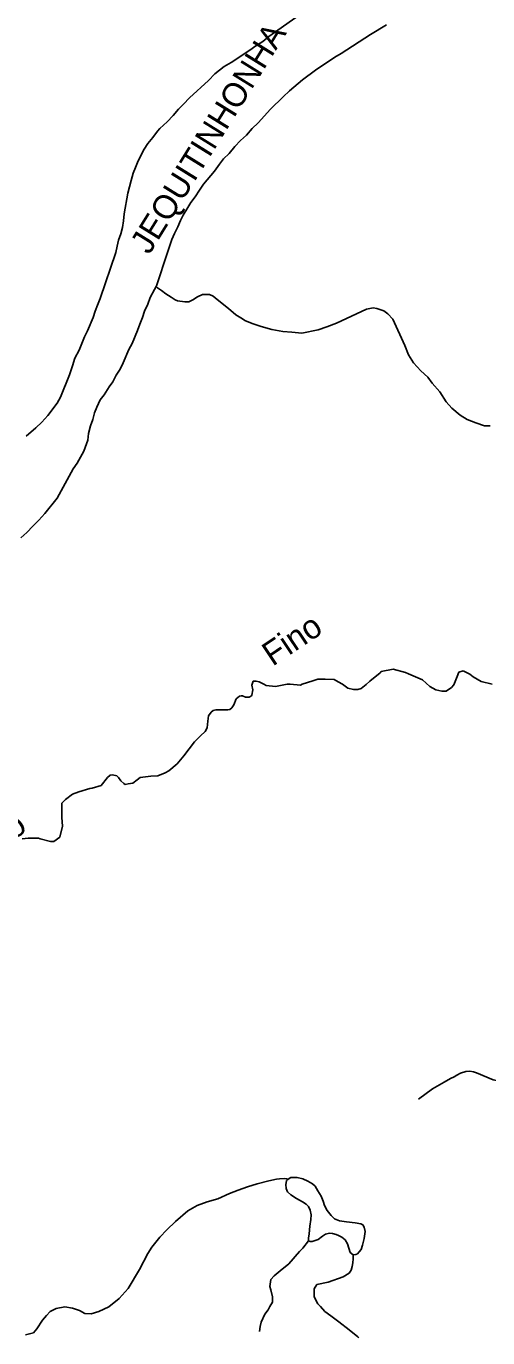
# Model space of a CAD drawing. Extents: x 436.3 to 500.4, y 8231 to 8286.4.
# Drawn here: x 485.33 to 489.18, y 8231.04 to 8241.98 of the extents above; entities that cross this region are included whole.
import ezdxf
from ezdxf.enums import TextEntityAlignment as Align

# ---------------------------------------------------------------- set-up
doc = ezdxf.new("R2010")
doc.units = 0
doc.header["$LTSCALE"] = 0.08
doc.linetypes.add('LONG_DASHED', pattern=[7.5, 6, -1.5])
doc.layers.add('2', color=7, linetype='Continuous', lineweight=25)
doc.layers.add('9', color=7, linetype='LONG_DASHED', lineweight=25)
doc.layers.add('61', color=7, linetype='Continuous')

msp = doc.modelspace()

# ---------------------------------------------------------------- linework, layer by layer
at = {"layer": '2'}
for points in [[(485.328, 8238.5583), (485.4095, 8238.6256), (485.4594, 8238.675), (485.5093, 8238.7289), (485.5864, 8238.8321), (485.6136, 8238.8815), (485.6881, 8239.0689), (485.7137, 8239.1424), (485.7347, 8239.2068), (485.7696, 8239.2757), (485.8137, 8239.3849), (485.8409, 8239.4343), (485.8864, 8239.5467), (485.9045, 8239.6007), (485.9227, 8239.6501), (485.9454, 8239.7041), (486.0754, 8240.0881), (486.086, 8240.1406), (486.0995, 8240.1901), (486.1176, 8240.2442), (486.1312, 8240.2982), (486.1403, 8240.3522), (486.1448, 8240.4108), (486.1764, 8240.582), (486.2035, 8240.6902), (486.2215, 8240.7488), (486.2395, 8240.7983), (486.2621, 8240.8524), (486.3117, 8240.9515), (486.3433, 8240.9966), (486.3839, 8241.0461), (486.4245, 8241.1001), (486.4425, 8241.1227), (486.5057, 8241.1767), (486.5553, 8241.2307), (486.6004, 8241.2848), (486.6409, 8241.3253), (486.6905, 8241.3793), (486.8483, 8241.5235), (486.9023, 8241.5775), (486.9789, 8241.6406), (487.0376, 8241.6721), (487.1953, 8241.7756), (487.2448, 8241.8117), (487.3034, 8241.8477), (487.3529, 8241.8882), (487.6255, 8242.0822)], [(486.4121, 8239.8049), (486.416, 8239.812), (486.5076, 8240.0897), (486.5425, 8240.1982), (486.5651, 8240.2477), (486.5922, 8240.3017), (486.6148, 8240.3558), (486.6374, 8240.4008), (486.669, 8240.4503), (486.7006, 8240.5043), (486.7368, 8240.5538), (486.7729, 8240.6079), (486.809, 8240.6574), (486.8992, 8240.7654), (486.9398, 8240.824), (486.9759, 8240.869), (487.021, 8240.914), (487.0705, 8240.9726), (487.1156, 8241.0221), (487.1652, 8241.0672), (487.2147, 8241.1212), (487.2643, 8241.1708), (487.3678, 8241.2835), (487.4713, 8241.3871), (487.5253, 8241.4367), (487.6333, 8241.5269), (487.7413, 8241.6081), (487.9033, 8241.7163), (487.9572, 8241.7479), (488.2, 8241.9058), (488.3349, 8241.987)], [(485.2845, 8237.7095), (485.3343, 8237.7544), (485.3842, 8237.8082), (485.4341, 8237.8575), (485.484, 8237.9114), (485.5861, 8238.0404), (485.7211, 8238.2837), (485.752, 8238.3332), (485.8087, 8238.4329), (485.8436, 8238.5247), (485.8477, 8238.5801), (485.866, 8238.643), (485.8842, 8238.6969), (485.8979, 8238.7508), (485.9162, 8238.8002), (485.9457, 8238.8597), (485.9782, 8238.901), (486.02, 8238.9677), (486.0502, 8239.0113), (486.0796, 8239.0652), (486.1114, 8239.1146), (486.1386, 8239.1685), (486.1841, 8239.2808), (486.2113, 8239.3302), (486.2568, 8239.4381), (486.275, 8239.492), (486.2977, 8239.546), (486.3158, 8239.5999), (486.343, 8239.6584), (486.3612, 8239.7123), (486.3987, 8239.7805), (486.4121, 8239.8049)], [(488.0579, 8231.7323), (488.0793, 8231.7345), (488.0922, 8231.7409), (488.1071, 8231.7559), (488.1221, 8231.7773), (488.1349, 8231.8116), (488.1498, 8231.8693), (488.1561, 8231.9271), (488.1474, 8231.9635), (488.1366, 8231.9827), (488.1216, 8231.9912), (488.0744, 8231.9976), (488.0015, 8232.006), (487.9414, 8232.0145), (487.9006, 8232.0315), (487.8726, 8232.0594), (487.8403, 8232.1021), (487.8187, 8232.1427), (487.8057, 8232.179), (487.7884, 8232.2196), (487.7626, 8232.2667), (487.7409, 8232.3031), (487.7172, 8232.3244), (487.6785, 8232.3457), (487.6377, 8232.365), (487.5904, 8232.3756), (487.5581, 8232.3778), (487.5336, 8232.3759), (487.5302, 8232.3744), (487.5112, 8232.3607)], [(487.5112, 8232.3607), (487.5002, 8232.3499), (487.496, 8232.3178), (487.4983, 8232.2856), (487.5091, 8232.2579), (487.5372, 8232.2323), (487.5845, 8232.2002), (487.634, 8232.1724), (487.6641, 8232.1554), (487.6835, 8232.134), (487.6986, 8232.1041), (487.7052, 8232.0656), (487.7031, 8232.027), (487.6946, 8231.9715), (487.6883, 8231.9073), (487.6831, 8231.8705), (487.6847, 8231.8492)], [(487.6847, 8231.8492), (487.6992, 8231.8431), (487.7142, 8231.8431), (487.7314, 8231.8474), (487.7636, 8231.8603), (487.8, 8231.8881), (487.8257, 8231.9052), (487.8601, 8231.9118), (487.8837, 8231.9096), (487.9138, 8231.9011), (487.9352, 8231.8926), (487.9611, 8231.8797), (487.9889, 8231.8563), (488.0083, 8231.8242), (488.0192, 8231.7879), (488.032, 8231.7515), (488.0579, 8231.7323)]]:
    msp.add_lwpolyline(points, dxfattribs=at)
at = {"layer": '9'}
msp.add_line((486.4231, 8239.7953), (486.4121, 8239.8049), dxfattribs=at)
for points in [[(489.2012, 8238.6429), (489.1521, 8238.6448), (489.0805, 8238.6672), (489.007, 8238.6956), (488.9498, 8238.7323), (488.8804, 8238.7914), (488.8336, 8238.8443), (488.7807, 8238.9259), (488.7172, 8239.0005), (488.6805, 8239.0494), (488.6214, 8239.1025), (488.5602, 8239.1697), (488.5173, 8239.2351), (488.4869, 8239.3127), (488.3878, 8239.5318), (488.345, 8239.5786), (488.3122, 8239.6032), (488.2528, 8239.6216), (488.2241, 8239.6276), (488.1667, 8239.6174), (487.9162, 8239.4987), (487.8381, 8239.468), (487.7641, 8239.4435), (487.6285, 8239.417), (487.5443, 8239.4231), (487.4703, 8239.4313), (487.3784, 8239.4462), (487.29, 8239.4708), (487.2222, 8239.4934), (487.1585, 8239.5201), (487.1195, 8239.5426), (487.0784, 8239.5693), (487.0168, 8239.6205), (486.9222, 8239.6964), (486.8873, 8239.7252), (486.8585, 8239.7375), (486.8338, 8239.7396), (486.7988, 8239.7376), (486.7576, 8239.7192), (486.7184, 8239.6947), (486.6855, 8239.6784), (486.6505, 8239.6764), (486.5908, 8239.6847), (486.5723, 8239.6929), (486.5373, 8239.7155), (486.4941, 8239.7443), (486.4571, 8239.771), (486.4231, 8239.7953)], [(486.369, 8235.7223), (486.4269, 8235.7262), (486.4885, 8235.7491), (486.5193, 8235.7683), (486.5888, 8235.8257), (486.6428, 8235.8908), (486.7315, 8236.0094), (486.7831, 8236.0601), (486.8217, 8236.0946), (486.8371, 8236.1252), (486.8449, 8236.1825), (486.8488, 8236.2247), (486.872, 8236.2552), (486.8874, 8236.2706), (486.9106, 8236.2744), (487.0107, 8236.2744), (487.0261, 8236.2783), (487.0454, 8236.2936), (487.0608, 8236.3165), (487.0802, 8236.3662), (487.1072, 8236.3892), (487.1225, 8236.3931), (487.1342, 8236.3931), (487.1572, 8236.3816), (487.188, 8236.3817), (487.2073, 8236.3931), (487.2112, 8236.3969), (487.219, 8236.4429), (487.2113, 8236.4811), (487.2229, 8236.5156), (487.2461, 8236.5156), (487.2729, 8236.5079), (487.3115, 8236.4888), (487.3314, 8236.4783), (487.4084, 8236.4707), (487.5046, 8236.49), (487.5315, 8236.49), (487.6162, 8236.4824), (487.6316, 8236.4901), (487.7201, 8236.5169), (487.7625, 8236.5323), (487.824, 8236.5324), (487.8971, 8236.5286), (487.9317, 8236.5095), (487.9663, 8236.4905), (488.0122, 8236.4561), (488.0584, 8236.4447), (488.0968, 8236.4447), (488.1237, 8236.4525), (488.1661, 8236.4869), (488.1969, 8236.5138), (488.283, 8236.5834), (488.2908, 8236.5948), (488.3907, 8236.6141), (488.4944, 8236.5875), (488.5173, 8236.5761), (488.6363, 8236.5266), (488.6977, 8236.4694), (488.7475, 8236.4427), (488.7973, 8236.4314), (488.8319, 8236.4314), (488.878, 8236.4621), (488.8972, 8236.4851), (488.9242, 8236.554), (488.9396, 8236.5884), (488.9742, 8236.5999), (489.0316, 8236.5734), (489.0585, 8236.5505), (489.1236, 8236.5124), (489.2156, 8236.4897)], [(485.2949, 8235.1998), (485.345, 8235.207), (485.431, 8235.207), (485.4454, 8235.1998), (485.5313, 8235.1785), (485.56, 8235.1785), (485.61, 8235.214), (485.6314, 8235.3064), (485.6242, 8235.3775), (485.6241, 8235.4983), (485.6555, 8235.5273), (485.7135, 8235.5732), (485.7674, 8235.5923), (485.86, 8235.6191), (485.8793, 8235.6229), (485.9526, 8235.6458), (486.0066, 8235.7109), (486.0297, 8235.73), (486.0489, 8235.7339), (486.0837, 8235.7262), (486.0991, 8235.7108), (486.1184, 8235.6841), (486.1415, 8235.6612)], [(486.1415, 8235.6612), (486.1531, 8235.6535), (486.1801, 8235.6573), (486.2186, 8235.665), (486.2533, 8235.6918), (486.2804, 8235.7108), (486.369, 8235.7223)], [(488.6007, 8233.03), (488.7193, 8233.1145), (488.8148, 8233.1721), (488.8684, 8233.2028), (488.8991, 8233.2149), (488.9219, 8233.2296), (488.9525, 8233.2451), (488.9969, 8233.2605), (489.0291, 8233.2643), (489.0616, 8233.2571), (489.0866, 8233.2492), (489.2247, 8233.1921), (489.2898, 8233.177), (489.3702, 8233.1619), (489.4008, 8233.1657), (489.4398, 8233.1891)], [(485.3235, 8231.0657), (485.3881, 8231.0817), (485.4164, 8231.114), (485.4648, 8231.1863), (485.497, 8231.2266), (485.5293, 8231.2588), (485.5778, 8231.283), (485.6506, 8231.299), (485.7154, 8231.287), (485.7721, 8231.2668), (485.8167, 8231.2427), (485.8692, 8231.2386), (485.934, 8231.2588), (486.0188, 8231.299), (486.1036, 8231.3674), (486.1803, 8231.4519), (486.2747, 8231.6105), (486.3432, 8231.7433), (486.3754, 8231.7956), (486.3996, 8231.8238), (486.444, 8231.8801), (486.5005, 8231.9405), (486.5731, 8232.0089), (486.678, 8232.0975), (486.7548, 8232.1418), (486.8396, 8232.1741), (486.9286, 8232.1983), (487.0255, 8232.2426), (487.0983, 8232.2708), (487.175, 8232.299), (487.2558, 8232.3232), (487.3528, 8232.3474), (487.4173, 8232.3636), (487.4421, 8232.3664), (487.485, 8232.3672), (487.5009, 8232.366), (487.5112, 8232.3607)], [(487.2748, 8231.0918), (487.2819, 8231.1353), (487.2892, 8231.1715), (487.3182, 8231.2367), (487.3472, 8231.2729), (487.3617, 8231.3019), (487.3834, 8231.3382), (487.3834, 8231.3816), (487.3687, 8231.4396), (487.3614, 8231.4685), (487.3686, 8231.5264), (487.3976, 8231.5555), (487.4485, 8231.599), (487.5211, 8231.6569), (487.6082, 8231.7584), (487.6372, 8231.7874), (487.6847, 8231.8492)], [(488.0579, 8231.7323), (488.0562, 8231.6972), (488.0533, 8231.6647), (488.0474, 8231.6351), (488.0386, 8231.6027), (488.0228, 8231.5778), (487.972, 8231.5488), (487.8486, 8231.5052), (487.754, 8231.4833), (487.7323, 8231.4471), (487.7324, 8231.3964), (487.7324, 8231.3819), (487.7616, 8231.324), (487.7835, 8231.3023), (487.8198, 8231.2589), (487.8707, 8231.2227), (487.9362, 8231.1721), (488.0235, 8231.107), (488.0962, 8231.0492), (488.1052, 8231.0403)]]:
    msp.add_lwpolyline(points, dxfattribs=at)

# ---------------------------------------------------------------- texts
at = {"layer": '61'}
for s, rotation, p in [('RIO                                    JEQUITINHONHA', 58.212, (486.1003, 8239.6531)), ('Córrego                                 Fino', 33.776, (486.18, 8235.8288))]:
    msp.add_text(s, height=0.2, rotation=rotation, dxfattribs=at).set_placement(p, align=Align.CENTER)

doc.saveas('drawing.dxf')
